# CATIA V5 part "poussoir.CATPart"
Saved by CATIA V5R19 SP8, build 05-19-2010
Part number: CE8 Poussoir
Revision: ANY
Definition: UNKNOWN
Nomenclature: poussoir
Source: Unknown
Bounding box of the stored display mesh (mm): x 122.76 to 143.838, y 11.5 to 33.5, z 0 to 6
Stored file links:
  D:\Documents\1_Travail\1 - ac-limoges.fr\ac-limoges.fr\Emmanuel Maynard - STI2D_Turgot\2 -2I2D\2_SEQUENCE_Serrure_Biométrique\5-Spé_ITEC\Serrure_Bio_Eleve\poussoir.CATPart
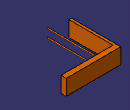
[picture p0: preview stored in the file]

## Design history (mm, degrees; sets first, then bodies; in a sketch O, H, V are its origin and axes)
Body1 "Extrusion2" (main body)
  Solid1: solid without history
